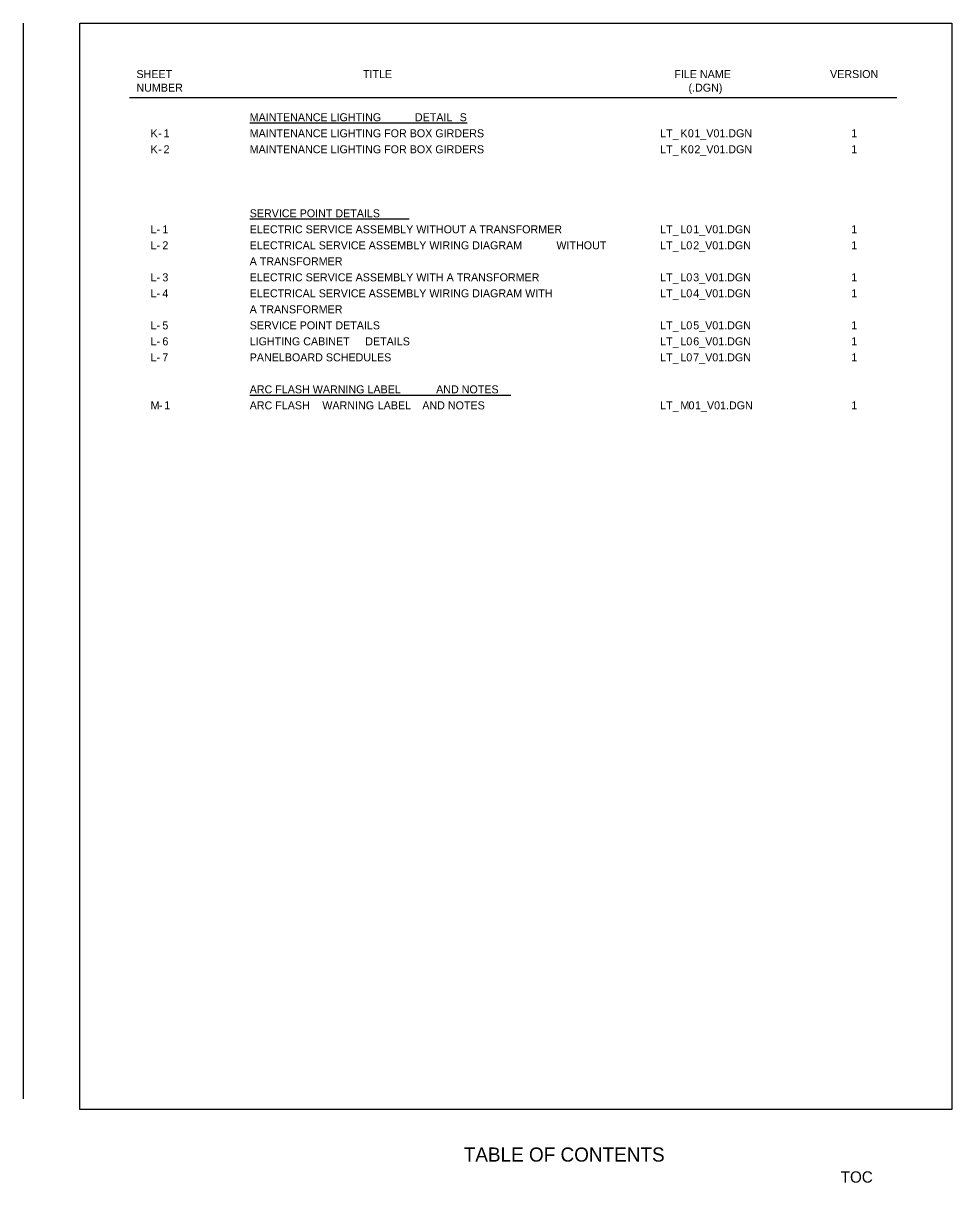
# Model space of a CAD drawing. Extents: x -39 to 780, y -523 to 2.
# Drawn here: x 370 to 780, y -511 to 2 of the extents above; entities that cross this region are included whole.
import ezdxf

# ---------------------------------------------------------------- set-up
doc = ezdxf.new("R2010")
doc.units = 0
for name, color, linetype in [('Miscellaneous2', 7, 'Continuous'), ('NonPlottingEle_dp', 7, 'Continuous'), ('PlotBorder_dp', 7, 'Continuous'), ('SheetLines_dp', 7, 'Continuous'), ('XSCell', 7, 'Continuous')]:
    doc.layers.add(name, color=color, linetype=linetype)

msp = doc.modelspace()

# ---------------------------------------------------------------- linework, layer by layer
at = {"layer": 'Miscellaneous2'}
msp.add_lwpolyline([(394.57, 1.53), (779.57, 1.53), (779.57, -478.47), (394.57, -478.47)], close=True, dxfattribs=at)
at = {"layer": 'NonPlottingEle_dp'}
for p, q in [((469.57, -42.55), (565.52, -42.55)), ((539.93, -84.98), (469.57, -84.98)), ((539.93, -84.98), (539.93, -84.98)), ((469.57, -162.76), (584.94, -162.76))]:
    msp.add_line(p, q, dxfattribs=at)
at = {"layer": 'SheetLines_dp'}
for p, q in [((369.57, 1.53), (369.57, -473.67)), ((416.5, -31.36), (755.28, -31.36))]:
    msp.add_line(p, q, dxfattribs=at)

# ---------------------------------------------------------------- texts
at = {"layer": 'NonPlottingEle_dp'}
for s, height, p in [('SHEET', 3.535, (419.57, -22.71)), ('TITLE', 3.535, (519.57, -22.71)), ('FILE NAME', 3.535, (657.07, -22.71)), ('VERSION', 3.535, (725.82, -22.71)), ('NUMBER', 3.535, (419.57, -28.72)), ('(.DGN)', 3.535, (663.32, -28.72)), ('MAINTENANCE LIGHTING', 3.5354, (469.57, -41.8)), ('DETAIL', 3.535, (542.52, -41.8)), ('S', 3.54, (562.28, -41.8)), ('K', 3.54, (425.82, -48.88)), ('1', 3.54, (431.53, -48.88)), ('MAINTENANCE LIGHTING FOR BOX GIRDERS', 3.5354, (469.57, -48.88)), ('LT_', 3.535, (650.82, -48.88)), ('K', 3.54, (659.73, -48.88)), ('0', 3.54, (663.04, -48.88)), ('1_V01.DGN', 3.535, (665.91, -48.88)), ('1', 3.54, (735.2, -48.88)), ('-', 3.54, (429.13, -48.88)), ('K', 3.54, (425.82, -55.95)), ('-', 3.54, (429.13, -55.95)), ('2', 3.54, (431.53, -55.95)), ('MAINTENANCE LIGHTING FOR BOX GIRDERS', 3.5354, (469.57, -55.95)), ('LT_', 3.535, (650.82, -55.95)), ('K', 3.54, (659.73, -55.95)), ('0', 3.54, (663.04, -55.95)), ('2_V01.DGN', 3.535, (665.91, -55.95)), ('1', 3.54, (735.2, -55.95)), ('SERVICE POINT DETAILS', 3.5354, (469.57, -84.23)), ('L-', 3.535, (425.82, -91.3)), ('1', 3.54, (431.02, -91.3)), ('ELECTRIC SERVICE ASSEMBLY WITHOUT A TRANSFORMER', 3.5354, (469.57, -91.3)), ('LT_', 3.535, (650.82, -91.3)), ('L0', 3.535, (659.73, -91.3)), ('1_V01.DGN', 3.535, (665.41, -91.3)), ('1', 3.54, (735.2, -91.3)), ('L-', 3.535, (425.82, -98.37)), ('2', 3.54, (431.02, -98.37)), ('ELECTRICAL SERVICE ASSEMBLY WIRING DIAGRAM', 3.5354, (469.57, -98.37)), (' WITHOUT ', 3.535, (603.68, -98.37)), ('LT_', 3.535, (650.82, -98.37)), ('L0', 3.535, (659.73, -98.37)), ('2_V01.DGN', 3.535, (665.41, -98.37)), ('1', 3.54, (735.2, -98.37)), ('A TRANSFORMER', 3.5354, (469.57, -105.44)), ('L-', 3.535, (425.82, -112.51)), ('3', 3.54, (431.02, -112.51)), ('ELECTRIC SERVICE ASSEMBLY WITH A TRANSFORMER', 3.5354, (469.57, -112.51)), ('LT_', 3.535, (650.82, -112.51)), ('L0', 3.535, (659.73, -112.51)), ('3_V01.DGN', 3.535, (665.41, -112.51)), ('1', 3.54, (735.2, -112.51)), ('L-', 3.535, (425.82, -119.58)), ('4', 3.54, (431.02, -119.58)), ('ELECTRICAL SERVICE ASSEMBLY WIRING DIAGRAM WITH', 3.5354, (469.57, -119.58)), ('LT_', 3.535, (650.82, -119.58)), ('L0', 3.535, (659.73, -119.58)), ('4_V01.DGN', 3.535, (665.41, -119.58)), ('1', 3.54, (735.2, -119.58)), ('A TRANSFORMER', 3.5354, (469.57, -126.65)), ('L-', 3.535, (425.82, -133.72)), ('5', 3.54, (431.02, -133.72)), ('SERVICE POINT DETAILS', 3.5354, (469.57, -133.72)), ('LT_', 3.535, (650.82, -133.72)), ('L0', 3.535, (659.73, -133.72)), ('5_V01.DGN', 3.535, (665.41, -133.72)), ('1', 3.54, (735.2, -133.72)), ('L-', 3.535, (425.82, -140.79)), ('6', 3.54, (431.02, -140.79)), ('LIGHTING CABINET', 3.5354, (469.57, -140.79)), (' DETAILS', 3.535, (519.29, -140.79)), ('LT_', 3.535, (650.82, -140.79)), ('L0', 3.535, (659.73, -140.79)), ('6_V01.DGN', 3.535, (665.41, -140.79)), ('1', 3.54, (735.2, -140.79)), ('L-', 3.535, (425.82, -147.87)), ('7', 3.54, (431.02, -147.87)), ('PANELBOARD SCHEDULES', 3.5354, (469.57, -147.87)), ('LT_', 3.535, (650.82, -147.87)), ('L0', 3.535, (659.73, -147.87)), ('7_V01.DGN', 3.535, (665.41, -147.87)), ('1', 3.54, (735.2, -147.87)), ('ARC FLASH WARNING LABEL ', 3.5354, (469.57, -162.01)), ('AND NOTES', 3.535, (551.89, -162.01)), ('M', 3.54, (425.82, -169.08)), ('-', 3.54, (429.42, -169.08)), ('1', 3.54, (431.82, -169.08)), ('ARC FLASH ', 3.535, (469.57, -169.08)), ('WARNING', 3.535, (501.64, -169.08)), (' LABEL ', 3.535, (524.8, -169.08)), ('AND NOTES', 3.535, (545.78, -169.08)), ('LT_', 3.535, (650.82, -169.08)), ('M', 3.54, (659.73, -169.08)), ('0', 3.54, (663.33, -169.08)), ('1_V01.DGN', 3.535, (666.2, -169.08)), ('1', 3.54, (735.2, -169.08))]:
    msp.add_text(s, height=height, dxfattribs=at).set_placement(p)
at = {"layer": 'PlotBorder_dp'}
msp.add_text(' TOC  ', height=5, dxfattribs=at).set_placement((728.7, -510.72))
at = {"layer": 'XSCell'}
msp.add_text('      TABLE OF CONTENTS        ', height=6.25, dxfattribs=at).set_placement((550.15, -501.43))

doc.saveas('drawing.dxf')
